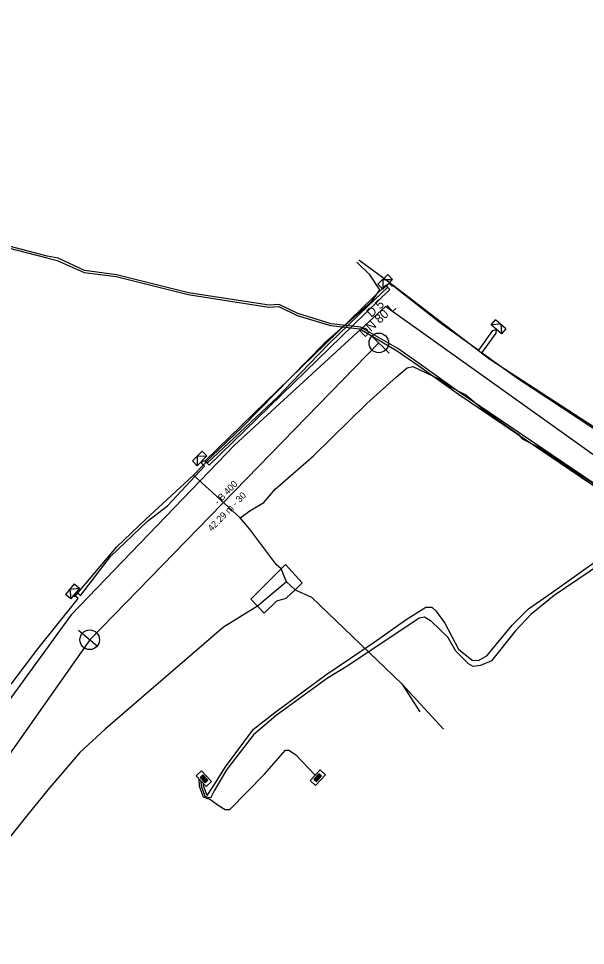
# Model space of a CAD drawing. Extents: x -600636 to -600148, y -1203980 to -1203569.
# Drawn here: x -600483.1 to -600425.2, y -1203834.8 to -1203740.1 of the extents above; entities that cross this region are included whole.
import ezdxf

# ---------------------------------------------------------------- set-up
doc = ezdxf.new("R2010")
doc.units = 0
for name, color, linetype in [('Cetin kolektor kabelovod', 7, 'Continuous'), ('Cetin nezaměřený', 7, 'Continuous'), ('Cetin NN přípojka', 7, 'Continuous'), ('Cetin zam průběh', 7, 'Continuous'), ('EON objekty', 7, 'Continuous'), ('EON podzemní NN', 7, 'Continuous'), ('EON podzemní VN', 7, 'Continuous'), ('Implicitní', 7, 'Continuous'), ('VaK Břeclav_kanalizace', 7, 'Continuous'), ('Vak Břeclav_vodovod', 7, 'Continuous'), ('Vrstva 9', 7, 'Continuous')]:
    doc.layers.add(name, color=color, linetype=linetype)

# ---------------------------------------------------------------- blocks, each defined once
blk = doc.blocks.new('NN630')
at = {"layer": 'Vrstva 9'}
for points in [[(-0.003, -0.7), (-0.703, 0)], [(-0.703, -0.7), (-0.703, 0), (0.697, 0), (0.697, -0.7)], [(-0.703, -0.7), (0.697, -0.7)], [(-0.003, -0.7), (0.697, 0)]]:
    blk.add_lwpolyline(points, dxfattribs=at)
blk = doc.blocks.new('NN620')
at = {"layer": 'EON objekty'}
for points in [[(0.752, 0.004), (-0.748, 0.004)], [(-0.748, 0.004), (-0.748, -0.746)], [(0.752, -0.746), (0.752, 0.004)], [(-0.748, -0.746), (0.752, -0.746)], [(0.368, -0.18), (-0.376, -0.18)], [(-0.376, -0.18), (-0.376, -0.558)], [(-0.376, -0.558), (0.368, -0.558)], [(0.321, -0.227), (-0.329, -0.227)], [(-0.329, -0.227), (-0.329, -0.51)], [(-0.329, -0.51), (0.321, -0.51)], [(0.274, -0.274), (-0.281, -0.274)], [(-0.281, -0.274), (-0.281, -0.463)], [(-0.281, -0.463), (0.274, -0.463)], [(0.227, -0.321), (-0.234, -0.321)], [(-0.234, -0.321), (-0.234, -0.416)], [(-0.234, -0.416), (0.227, -0.416)], [(-0.193, -0.369), (0.185, -0.369)], [(0.227, -0.416), (0.227, -0.321)], [(0.274, -0.463), (0.274, -0.274)], [(0.321, -0.51), (0.321, -0.227)], [(0.368, -0.558), (0.368, -0.18)]]:
    blk.add_lwpolyline(points, dxfattribs=at)
blk = doc.blocks.new('MoSymbol 2')
at = {"layer": 'Implicitní'}
blk.add_line((0, 0.0005), (0, -0.00075), dxfattribs=at)
blk.add_circle((0, 0), 0.0005, dxfattribs=at)

msp = doc.modelspace()

# ---------------------------------------------------------------- linework, layer by layer
at = {"layer": 'Cetin kolektor kabelovod'}
for points in [[(-600456.27, -1203796.31), (-600456.73, -1203795.91), (-600459.49, -1203792.23)], [(-600454.83, -1203798.45), (-600453.17, -1203799.19), (-600443.93, -1203808.05)], [(-600458.68, -1203800.12), (-600462.14, -1203802.25), (-600474.23, -1203812.68), (-600476.82, -1203815.05), (-600480.09, -1203818.86), (-600482.26, -1203821.55), (-600485.61, -1203825.73), (-600486.63, -1203826.86), (-600489.37, -1203830.16), (-600491.81, -1203833.43)]]:
    msp.add_lwpolyline(points, dxfattribs=at)
msp.add_lwpolyline([(-600455.83, -1203795.87), (-600456.27, -1203796.31), (-600459.37, -1203799.4), (-600458.68, -1203800.12), (-600457.98, -1203800.84), (-600456.71, -1203799.56), (-600455.73, -1203799.3), (-600454.83, -1203798.45), (-600454.1, -1203797.75), (-600455.83, -1203795.87)], close=True, dxfattribs=at)
at = {"layer": 'Cetin nezaměřený'}
for points in [[(-600455.71, -1203797.64), (-600456.27, -1203796.31), (-600456.73, -1203795.91), (-600459.49, -1203792.23)], [(-600455.71, -1203797.64), (-600458.68, -1203800.12), (-600462.14, -1203802.25), (-600474.23, -1203812.68), (-600476.82, -1203815.05), (-600480.09, -1203818.86), (-600482.26, -1203821.55), (-600485.61, -1203825.73), (-600489.37, -1203830.16), (-600491.81, -1203833.43), (-600492.338, -1203834.75)], [(-600455.71, -1203797.64), (-600454.83, -1203798.45), (-600453.17, -1203799.19), (-600443.93, -1203808.05)], [(-600443.93, -1203808.05), (-600439.7, -1203812.67)], [(-600443.93, -1203808.05), (-600442.086, -1203810.898)]]:
    msp.add_lwpolyline(points, dxfattribs=at)
at = {"layer": 'Cetin NN přípojka'}
for points in [[(-600455.71, -1203797.64), (-600458.68, -1203800.12), (-600462.14, -1203802.25), (-600474.23, -1203812.68), (-600476.82, -1203815.05), (-600480.09, -1203818.86), (-600482.26, -1203821.55), (-600485.61, -1203825.73), (-600489.37, -1203830.16), (-600491.81, -1203833.43), (-600492.338, -1203834.75)], [(-600455.71, -1203797.64), (-600454.83, -1203798.45), (-600453.17, -1203799.19), (-600443.93, -1203808.05)], [(-600443.93, -1203808.05), (-600439.7, -1203812.67)]]:
    msp.add_lwpolyline(points, dxfattribs=at)
at = {"layer": 'Cetin zam průběh'}
for points in [[(-600448.32, -1203764.77), (-600445.41, -1203766.9), (-600434.97, -1203774.92), (-600422.32, -1203783.12), (-600413.93, -1203789.04), (-600405.18, -1203794.93), (-600400.25, -1203797.98), (-600398.96, -1203798.36), (-600397.12, -1203797.36), (-600388.96, -1203781.95), (-600378.33, -1203762.13), (-600375.93, -1203758.23), (-600373.1, -1203754.01), (-600370.24, -1203749.96), (-600363.35, -1203740.04), (-600357.38, -1203731.69), (-600349.33, -1203720.15), (-600345.8, -1203715.19), (-600340.07, -1203706.96), (-600329.02, -1203689.27)], [(-600448.55, -1203765.01), (-600447.27, -1203766.25), (-600446.21, -1203767.84)], [(-600446.21, -1203767.84), (-600447.14, -1203769.15), (-600451.9, -1203773.36), (-600460.17, -1203781.78), (-600463.36, -1203784.86)], [(-600447.14, -1203769.15), (-600451.9, -1203773.36)], [(-600460.44, -1203791.11), (-600459.46, -1203790.39), (-600458.03, -1203789.53), (-600456.87, -1203788.19), (-600452.97, -1203784.79), (-600447.51, -1203779.45), (-600444.5, -1203776.72), (-600443.4, -1203775.81), (-600442.82, -1203775.66), (-600440.03, -1203777), (-600438.99, -1203777.73), (-600437.41, -1203778.55), (-600435.55, -1203780.1), (-600432.05, -1203782.55), (-600431.66, -1203783.05), (-600430.13, -1203783.84), (-600423.55, -1203788.15)], [(-600423.55, -1203788.15), (-600430.13, -1203783.84)], [(-600463.36, -1203784.86), (-600465.19, -1203786.74)], [(-600477.51, -1203798.97), (-600477.33, -1203799.12), (-600473.04, -1203794.08), (-600470.1, -1203791.26), (-600465.19, -1203786.74)], [(-600460.44, -1203791.11), (-600465.19, -1203786.74)], [(-600460.44, -1203791.11), (-600465.19, -1203786.74)], [(-600459.49, -1203792.23), (-600460.44, -1203791.11)]]:
    msp.add_lwpolyline(points, dxfattribs=at)
at = {"layer": 'EON podzemní NN'}
for points in [[(-600483.801, -1203808.07), (-600481.102, -1203804.461), (-600477.073, -1203799.464), (-600476.97, -1203799.333), (-600477.249, -1203799.111), (-600477.286, -1203798.816), (-600477.016, -1203798.78), (-600476.722, -1203799.019), (-600476.691, -1203798.98), (-600473.672, -1203795.059), (-600469.91, -1203791.43), (-600467.871, -1203789.879), (-600464.07, -1203785.817), (-600464.347, -1203785.548), (-600464.327, -1203785.286), (-600464.065, -1203785.278), (-600463.799, -1203785.523), (-600456.609, -1203778.75), (-600455.185, -1203777.274), (-600452.407, -1203774.395), (-600451.32, -1203773.27), (-600447.396, -1203769.512), (-600445.375, -1203767.577), (-600445.434, -1203767.516), (-600445.39, -1203767.27), (-600445.152, -1203767.233), (-600444.955, -1203767.436), (-600444.789, -1203767.441), (-600443.789, -1203768.219), (-600439.988, -1203771.191), (-600436.287, -1203773.861), (-600436.095, -1203774), (-600434.65, -1203771.98), (-600434.306, -1203771.872), (-600434.351, -1203772.251), (-600435.77, -1203774.235), (-600435.61, -1203774.35), (-600432.238, -1203776.781), (-600416.559, -1203787.121)], [(-600463.827, -1203819.443), (-600463.215, -1203818.526), (-600461.955, -1203816.525), (-600459.088, -1203812.688), (-600456.905, -1203810.982), (-600451.712, -1203807.127), (-600446.748, -1203803.782), (-600443.481, -1203801.477), (-600441.485, -1203800.213), (-600440.875, -1203800.229), (-600440.465, -1203800.586), (-600439.536, -1203801.867), (-600438.145, -1203804.516), (-600436.76, -1203805.634), (-600436.116, -1203805.68), (-600435.235, -1203805.157), (-600432.692, -1203802.07), (-600431.021, -1203800.385), (-600428.663, -1203798.755), (-600422.759, -1203794.567)], [(-600422.408, -1203794.985), (-600428.406, -1203799.034), (-600430.766, -1203800.969), (-600432.383, -1203802.666), (-600434.772, -1203805.7), (-600435.902, -1203806.189), (-600436.648, -1203806.285), (-600437.15, -1203806.016), (-600438.44, -1203804.723), (-600439.235, -1203803.28), (-600440.923, -1203801.7), (-600441.636, -1203801.236), (-600442.174, -1203801.336), (-600449.439, -1203806.213), (-600451.513, -1203807.458), (-600456.782, -1203811.281), (-600459.079, -1203813.257), (-600461.853, -1203816.815), (-600463.09, -1203818.969), (-600463.48, -1203819.73), (-600464, -1203819.56)], [(-600463.42, -1203819.89), (-600462.6, -1203820.51), (-600461.964, -1203820.858), (-600461.486, -1203820.874), (-600457.959, -1203817.264), (-600455.816, -1203814.832), (-600455.482, -1203814.811), (-600454.791, -1203815.27), (-600452.783, -1203817.366)], [(-600463.42, -1203819.89), (-600464.188, -1203819.627), (-600464.578, -1203818.54), (-600464.624, -1203817.759)], [(-600464, -1203819.56), (-600464.38, -1203818.5), (-600464.41, -1203817.99)], [(-600463.827, -1203819.443), (-600464.182, -1203818.46), (-600464.196, -1203818.225)]]:
    msp.add_lwpolyline(points, dxfattribs=at)
msp.add_lwpolyline([(-600445.584, -1203767.362), (-600445.148, -1203767.811), (-600463.59, -1203785.738), (-600464.026, -1203785.289)], close=True, dxfattribs=at)
at = {"layer": 'EON podzemní VN'}
for points in [[(-600501.847, -1203764.325), (-600497.959, -1203761.475), (-600496.908, -1203761.001), (-600494.282, -1203760.923), (-600480.162, -1203764.577), (-600479.132, -1203764.829), (-600476.382, -1203766.071), (-600473.11, -1203766.482), (-600465.75, -1203768.323), (-600457.511, -1203769.594), (-600456.508, -1203769.518), (-600454.624, -1203770.445), (-600451.211, -1203771.488), (-600448.233, -1203771.815), (-600444.486, -1203774.019), (-600442.217, -1203775.59), (-600438.167, -1203778.496), (-600424.472, -1203787.735), (-600416.801, -1203792.528), (-600411.123, -1203796.487), (-600404.975, -1203801.537), (-600404.82, -1203801.644), (-600404.96, -1203802.62)], [(-600424.36, -1203787.555), (-600438.08, -1203778.28), (-600442.027, -1203775.462), (-600444.357, -1203773.807), (-600448.151, -1203771.631), (-600451.152, -1203771.298), (-600454.57, -1203770.237), (-600456.457, -1203769.325), (-600457.482, -1203769.405), (-600465.732, -1203768.126), (-600473.064, -1203766.298), (-600476.316, -1203765.85), (-600479.036, -1203764.617), (-600480.143, -1203764.381), (-600494.25, -1203760.681)]]:
    msp.add_lwpolyline(points, dxfattribs=at)
at = {"layer": 'VaK Břeclav_kanalizace'}
for p, q in [((-600446.291, -1203773.251), (-600475.798, -1203803.548)), ((-600475.798, -1203803.548), (-600494.416, -1203830.039))]:
    msp.add_line(p, q, dxfattribs=at)
at = {"layer": 'Vak Břeclav_vodovod'}
msp.add_lwpolyline([(-600395.742, -1203804.116), (-600404.972, -1203798.52), (-600440.983, -1203772.83), (-600445.608, -1203769.543), (-600461.034, -1203783.688), (-600477.697, -1203801.016), (-600487.771, -1203814.834)], dxfattribs=at)

# ---------------------------------------------------------------- block references
at = {"layer": 'EON podzemní NN'}
for name, p, rotation in [('NN630', (-600445.39, -1203767.27), -136.2521416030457), ('NN630', (-600434.306, -1203771.872), 139.16664728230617), ('NN630', (-600464.328, -1203785.286), -134.3657555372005), ('NN630', (-600477.287, -1203798.816), -129.28333330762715), ('NN620', (-600464.41, -1203817.99), 132.8438695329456), ('NN620', (-600452.782, -1203817.367), 46.21052774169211)]:
    msp.add_blockref(name, p, dxfattribs=dict(at, rotation=rotation))
at = {"layer": 'VaK Břeclav_kanalizace', "yscale": 1999.7500312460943}
for p, xscale, rotation in [((-600446.291, -1203773.251), 1999.750031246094, 45.75677830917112), ((-600475.798, -1203803.548), 1999.7500312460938, -129.7207282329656)]:
    msp.add_blockref('MoSymbol 2', p, dxfattribs=dict(at, xscale=xscale, rotation=rotation))

# ---------------------------------------------------------------- texts
at = {"layer": 'VaK Břeclav_kanalizace'}
for s, height, p in [('- B 400', 0.6824, (-600462.7, -1203789.817)), ('42.29 m - 30', 0.68241, (-600463.345, -1203792.539))]:
    msp.add_text(s, height=height, rotation=45.75678, dxfattribs=at).set_placement(p)
at = {"layer": 'Vak Břeclav_vodovod'}
for s, p in [('D 5', (-600447.054, -1203770.692)), ('DN 80 L', (-600447.748, -1203772.74))]:
    msp.add_text(s, height=0.9099, rotation=42.51953, dxfattribs=at).set_placement(p)

doc.saveas('drawing.dxf')
